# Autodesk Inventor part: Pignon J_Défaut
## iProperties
Shininess: 64.0
Length Units: 11269
Angle Units: 11279
Time Units: 11290
Mass Units: 11283
Length Display Precision: 3
Angle Display Precision: 2
Compacted: True
Part Number: Pignon J_Défaut
Document SubType Name: Modeling
Created: 2006-01
Material: Par défaut
Designer: Fricot
Density: 0.0
Volumn: 0.0
Area: 0.0
PropertySet Name: Model Information
Control State: 0
Master: False
Checked Out: False
Author: Fricot
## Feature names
1. Base1
